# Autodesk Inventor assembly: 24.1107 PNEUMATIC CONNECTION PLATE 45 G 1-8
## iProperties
Created: 2007-06
Part Number: 24.1107 PNEUMATIC CONNECTION PLATE 45 G 1-8
Document SubType Name: Assembly
Designer: Andy Moles
Author: Andy Moles
